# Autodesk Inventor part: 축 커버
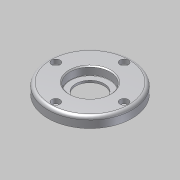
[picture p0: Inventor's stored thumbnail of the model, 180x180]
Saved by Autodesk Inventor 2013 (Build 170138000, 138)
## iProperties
Created: 2013-06
Part Number: 축 커버
Document SubType Name: Modeling
Designer: SeoGD™[esajin.kr]
Density: 1 g/cm^3
Material: 일반
Mass: 41.026 g
Surface Area: 133.703 cm^2
Volume: 41.026 cm^3
Author: SeoGD™[esajin.kr]
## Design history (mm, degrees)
sketch "스케치1"
  geometry: C1 r 40 at (0, 0) reference; C2 r 26 at (0, 0) reference; 1 further point
  node "참조1"
  node "참조2"
extrude "돌출1" new body sketch "스케치1" distance "d0" = 10; taper "d1" = 0 deg
extrude "돌출2" join sketch "스케치1" distance "d2" = 3; taper "d3" = 0 deg
hole "구멍1" diameter "d6" = 27; stored, may be unused: countersink angle "d10" = 90 deg, drill point angle "d12" = 118 deg; dims "d4" = 10, "d5" = 10, "d7" = 6, "d8" = 38, "d9" = 8, "d11" = 8
sketch "스케치2"
  geometry: C1 r 20 at (0, 0); 1 further point
  constraints: 1 centre point, 1 coincident
  dimensions: "d13" = 40 diameter of C1
extrude "돌출3" cut sketch "스케치2" distance "d14" = 3; taper "d15" = 0 deg
sketch "스케치3"
  geometry: C1 r 1.621 at (0, 32.5) reference; 1 further point
hole "구멍2" sketch "스케치3" at (0, 32.5) diameter "d16" = 4.5; stored, may be unused: countersink angle "d20" = 90 deg, drill point angle "d22" = 118 deg; dims "d17" = 6, "d18" = 8, "d19" = 4.4, "d21" = 8
fillet "모깎기1" dims "d26" = 3, "d27" = 0.3
chamfer "모따기1" distance "d28" = 1; stored, may be unused: second distance "d29" = 2, angle "d30" = 45 deg
node "솔리드1"
pattern_circular "원형 패턴1" dims angle "d24" = 360 deg
node "참조3"
